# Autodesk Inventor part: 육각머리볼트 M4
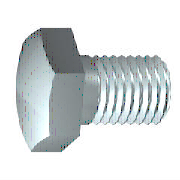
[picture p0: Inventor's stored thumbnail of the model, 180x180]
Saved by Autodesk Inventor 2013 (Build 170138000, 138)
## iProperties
Created: 2012-02
Part Number: 육각머리볼트 M4
Material: 스테인리스강
Description: 6각 머리 나사
Document SubType Name: Modeling
Standard: ISO 4017
Designer: mduedu
Standard Revision: Third edition 1999-08-15
Standards Organization: ISO
Language: ko-KR
Size Designation: M4 x 10
Categories: <MemberInstance><Categories><Category DisplayName="조임쇠" InternalName="e4da775c-781d-43d5-af7c-5136215cf5a6" Mnemonic="FSTN"><Category DisplayName="볼트" InternalN
Density: 8.08 g/cm^3
IsCustomPart: 0
Author: mduedu
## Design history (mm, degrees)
sketch "스케치1"
  geometry: L1 (0, 3.015)-(0, 2); L2 (1.75, 2)-(10, 2); L3 (10, 2)-(10, 0); L4 (10, 0)-(-0.4, 0); L5 (-2.48, 0)-(12.08, 0) reference; L6 (-0.4, 0)-(-0.4, 3.015); L7 (-0.4, 3.015)-(0, 3.015); L8 (1.75, 2)-(1.32, 2); L9 (1.32, 2)-(0, 2); L10 (0, -0.603)-(0, 3.618) reference
  constraints: 16 end point, 2 collinear, 2 perpendicular, 1 parallel
  dimensions: "d0" = 10 distance between parallel lines of L3 L1 (= NLG); "d1" = 8.25 distance from line of L2.start L3 (= GEL); "d2" = 4 diameter of L2 L4 (= GD); "d9" = 0.4001 distance between parallel lines of L6 L1 (computed from SD); "d10" = 6.03 diameter of L7 L4 (= SD2); "d13" = 0.42952 distance of L2.start L8.end (computed from GAL); "d14" = 4 diameter of L9 L4 (= BDM)
revolve "본체" sketch "스케치1" stored, may be unused: angle "d12" = 90 deg
sketch "스케치2"
  geometry: L1 (0, 4.041)-(3.5, 2.021); L2 (3.5, 2.021)-(3.5, -2.021); L3 (3.5, -2.021)-(0, -4.041); L4 (0, -4.041)-(-3.5, -2.021); L5 (-3.5, -2.021)-(-3.5, 2.021); L6 (-3.5, 2.021)-(0, 4.041); 2 further points
  constraints: 12 end point, 1 coincident, 1 vertical, 11 other
  dimensions: "d11" = 7 distance between parallel lines of L5 L2 (= SW)
extrude "머리" join sketch "스케치2" distance "d3" = 2.4 (= KOH - SD); taper "d4" = 0 deg
sketch "스케치4"
  geometry: L1 (-2.8, 3.5)-(-2.8, 4.041); L2 (-2.8, 4.041)-(-2.487, 4.041); L3 (-2.487, 4.041)-(-2.8, 3.5); L4 (-3.28, 0)-(0.08, 0) reference; L5 (-0.4, 4.041)-(-2.8, 4.041) reference; L6 (-2.8, 2.021)-(-2.8, 4.041) reference
  constraints: 6 end point, 2 collinear, 1 perpendicular, 1 vertical
  dimensions: "d5" = 30 deg angle of L3 L1 (= ANG1); "d19" = 7 diameter of L1.start L4 (= SW0)
revolve "모따기1" sketch "스케치4" stored, may be unused: angle "d21" = 90 deg
workplane "Work Plane1"
body "Solid1"
feature "스레드" dims "d15" = 8.25 (= GEL), "d16" = 0
chamfer "모따기2" distance "d6" = 0.42941 (= -0.5 x SPD + 0.5 x GD); stored, may be unused: second distance "d7" = 0.42952 (computed from GUL), angle "d55" = 45 deg
other parameters: "NLG" = 10 [user parameter; used in 1 equation term], "GD" = 4 (= NND) [user parameter; used in 2 equation terms], "BDM" = 4 (= NND) [user parameter; used in 1 equation term], "KOH" = 2.8 [user parameter; used in 1 equation term], "GEL" = 8.25 [user parameter; used in 2 equation terms], "SW" = 7 [user parameter; used in 2 equation terms], "SW0" = 7 (= SW) [user parameter; used in 1 equation term], "SPD" = 3.14117 (= NND - 1.2269 x PTC) [user parameter; used in 1 equation term], "SD2" = 6.03 [user parameter; used in 2 equation terms], "SD" = 0.4 [user parameter; used in 2 equation terms], "ANG1" = 30 deg [user parameter; used in 1 equation term], "GAL" = 0.42941 (= 0.61345 x PTC) [user parameter; used in 1 equation term], "GUL" = 0.42941 (= 0.61345 x PTC) [user parameter; used in 1 equation term], "d8" = 0, "RR" = 0.2 [user parameter], "d57" = 0, "d58" = 0, "TPU" = 14.28571 (computed from PTC) [user parameter], "GD1" = 3.14117 (= THREADDIA - 1.2269 x PTC) [user parameter], "THREADDIA" = 4 [user parameter; used in 1 equation term], "SDH" = 6.03 (= SD2) [user parameter], "SDHG" = 2.1 [user parameter], "TOA" = 30 deg [user parameter], "PTC" = 0.7 [user parameter; used in 5 equation terms], "NND" = 4 [user parameter; used in 3 equation terms], "E0" = 8.085 [user parameter]
